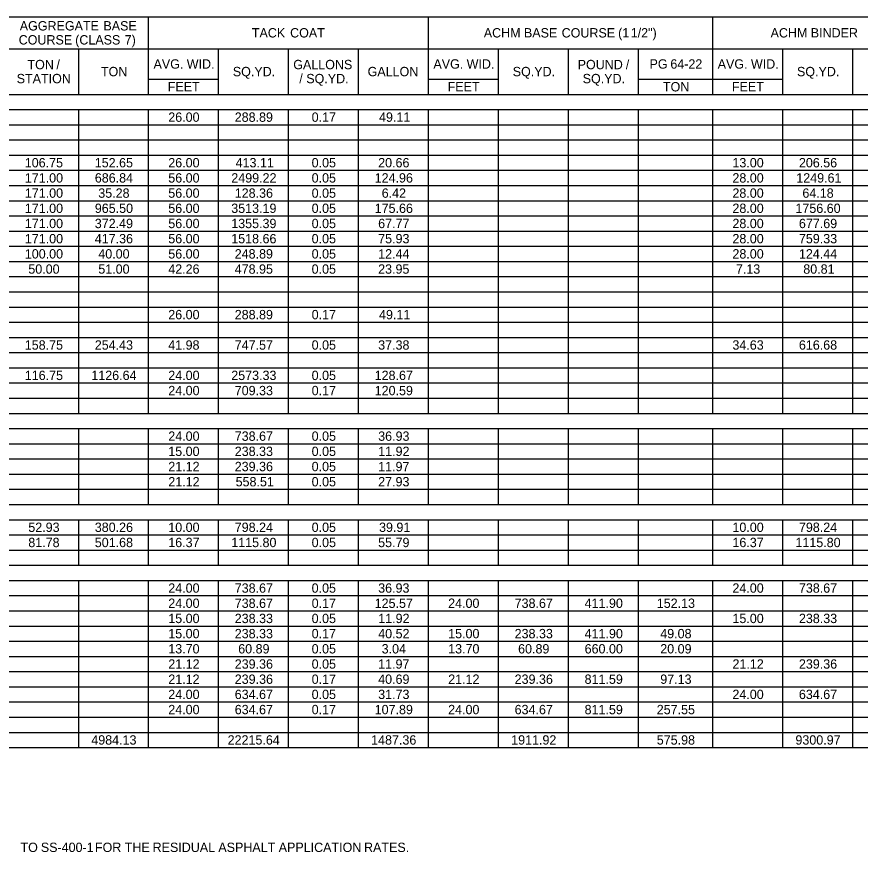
# Model space of a CAD drawing. Extents: x 1197542 to 1207068, y 230488 to 237324.
# Drawn here: x 1202093 to 1202635, y 231731 to 232267 of the extents above; entities that cross this region are included whole.
import ezdxf

# ---------------------------------------------------------------- set-up
doc = ezdxf.new("R2010")
doc.units = 0
doc.layers.add('Default', color=7, linetype='Continuous')

msp = doc.modelspace()

# ---------------------------------------------------------------- linework, layer by layer
at = {"layer": 'Default'}
for p, q in [((1201719.44, 232267.45), (1203261.96, 232267.45)), ((1202178.08, 232217.73), (1202178.08, 232267.45)), ((1202357.79, 232217.73), (1202357.79, 232267.45)), ((1202540.31, 232246.98), (1202540.31, 232267.45)), ((1202540.31, 232217.73), (1202540.31, 232267.45)), ((1202088.22, 232246.98), (1203261.96, 232246.98)), ((1202133.15, 232217.73), (1202133.15, 232246.98)), ((1202223, 232217.73), (1202223, 232246.98)), ((1202267.93, 232217.73), (1202267.93, 232246.98)), ((1202312.86, 232217.73), (1202312.86, 232246.98)), ((1202402.72, 232217.73), (1202402.72, 232246.98)), ((1202447.64, 232217.73), (1202447.64, 232246.98)), ((1202492.57, 232217.73), (1202492.57, 232246.98)), ((1202585.24, 232217.73), (1202585.24, 232246.98)), ((1202630.16, 232217.73), (1202630.16, 232246.98)), ((1202178.08, 232227.48), (1202223, 232227.48)), ((1202223, 232217.73), (1202223, 232227.48)), ((1202357.79, 232227.48), (1202402.72, 232227.48)), ((1202402.72, 232217.73), (1202402.72, 232227.48)), ((1202492.57, 232227.48), (1202585.24, 232227.48)), ((1202585.24, 232217.73), (1202585.24, 232227.48)), ((1201719.44, 232217.73), (1203261.96, 232217.73)), ((1202088.22, 232217.73), (1202223, 232217.73)), ((1202223, 232217.73), (1202402.72, 232217.73)), ((1202402.72, 232217.73), (1202585.24, 232217.73)), ((1202585.24, 232217.73), (1202767.76, 232217.73)), ((1201719.44, 232207.98), (1203261.96, 232207.98)), ((1202133.15, 232012.98), (1202133.15, 232207.98)), ((1202133.15, 232012.98), (1202133.15, 232207.98)), ((1202178.08, 232012.98), (1202178.08, 232207.98)), ((1202178.08, 232012.98), (1202178.08, 232207.98)), ((1202223, 232012.98), (1202223, 232207.98)), ((1202223, 232012.98), (1202223, 232207.98)), ((1202267.93, 232012.98), (1202267.93, 232207.98)), ((1202267.93, 232012.98), (1202267.93, 232207.98)), ((1202312.86, 232012.98), (1202312.86, 232207.98)), ((1202312.86, 232012.98), (1202312.86, 232207.98)), ((1202357.79, 232012.98), (1202357.79, 232207.98)), ((1202357.79, 232012.98), (1202357.79, 232207.98)), ((1202402.72, 232012.98), (1202402.72, 232207.98)), ((1202402.72, 232012.98), (1202402.72, 232207.98)), ((1202447.64, 232012.98), (1202447.64, 232207.98)), ((1202447.64, 232012.98), (1202447.64, 232207.98)), ((1202492.57, 232012.98), (1202492.57, 232207.98)), ((1202492.57, 232012.98), (1202492.57, 232207.98)), ((1202540.31, 232012.98), (1202540.31, 232207.98)), ((1202540.31, 232012.98), (1202540.31, 232207.98)), ((1202585.24, 232012.98), (1202585.24, 232207.98)), ((1202585.24, 232012.98), (1202585.24, 232207.98)), ((1202630.16, 232012.98), (1202630.16, 232207.98)), ((1202630.16, 232012.98), (1202630.16, 232207.98)), ((1201719.44, 232198.23), (1203261.96, 232198.23)), ((1201719.44, 232188.48), (1203261.96, 232188.48)), ((1201719.44, 232178.73), (1203261.96, 232178.73)), ((1201719.44, 232168.98), (1203261.96, 232168.98)), ((1201719.44, 232159.23), (1203261.96, 232159.23)), ((1201719.44, 232149.48), (1203261.96, 232149.48)), ((1201719.44, 232139.73), (1203261.96, 232139.73)), ((1201719.44, 232129.98), (1203261.96, 232129.98)), ((1201719.44, 232120.23), (1203261.96, 232120.23)), ((1201719.44, 232110.48), (1203261.96, 232110.48)), ((1201719.44, 232100.73), (1203261.96, 232100.73)), ((1201719.44, 232090.98), (1203261.96, 232090.98)), ((1201719.44, 232081.23), (1203261.96, 232081.23)), ((1201719.44, 232071.48), (1203261.96, 232071.48)), ((1201719.44, 232061.73), (1203261.96, 232061.73)), ((1201719.44, 232051.98), (1203261.96, 232051.98)), ((1201719.44, 232042.23), (1203261.96, 232042.23)), ((1201719.44, 232032.48), (1203261.96, 232032.48)), ((1201719.44, 232022.73), (1203261.96, 232022.73)), ((1201719.44, 232012.98), (1202992.4, 232012.98)), ((1201719.44, 232012.98), (1203261.96, 232012.98)), ((1201719.44, 232003.23), (1203261.96, 232003.23)), ((1202133.15, 231954.48), (1202133.15, 232003.23)), ((1202133.15, 231954.48), (1202133.15, 232003.23)), ((1202178.08, 231954.48), (1202178.08, 232003.23)), ((1202178.08, 231954.48), (1202178.08, 232003.23)), ((1202223, 231954.48), (1202223, 232003.23)), ((1202223, 231954.48), (1202223, 232003.23)), ((1202267.93, 231954.48), (1202267.93, 232003.23)), ((1202267.93, 231954.48), (1202267.93, 232003.23)), ((1202312.86, 231954.48), (1202312.86, 232003.23)), ((1202312.86, 231954.48), (1202312.86, 232003.23)), ((1202357.79, 231954.48), (1202357.79, 232003.23)), ((1202357.79, 231954.48), (1202357.79, 232003.23)), ((1202402.72, 231954.48), (1202402.72, 232003.23)), ((1202402.72, 231954.48), (1202402.72, 232003.23)), ((1202447.64, 231954.48), (1202447.64, 232003.23)), ((1202447.64, 231954.48), (1202447.64, 232003.23)), ((1202492.57, 231954.48), (1202492.57, 232003.23)), ((1202492.57, 231954.48), (1202492.57, 232003.23)), ((1202540.31, 231954.48), (1202540.31, 232003.23)), ((1202540.31, 231954.48), (1202540.31, 232003.23)), ((1202585.24, 231954.48), (1202585.24, 232003.23)), ((1202585.24, 231954.48), (1202585.24, 232003.23)), ((1202630.16, 231954.48), (1202630.16, 232003.23)), ((1202630.16, 231954.48), (1202630.16, 232003.23)), ((1201719.44, 231993.48), (1203261.96, 231993.48)), ((1201719.44, 231983.73), (1203261.96, 231983.73)), ((1201719.44, 231973.98), (1203261.96, 231973.98)), ((1201719.44, 231964.23), (1203261.96, 231964.23)), ((1201719.44, 231954.48), (1203261.96, 231954.48)), ((1201719.44, 231954.48), (1203261.96, 231954.48)), ((1201719.44, 231944.73), (1203261.96, 231944.73)), ((1202133.15, 231915.48), (1202133.15, 231944.73)), ((1202133.15, 231915.48), (1202133.15, 231944.73)), ((1202178.08, 231915.48), (1202178.08, 231944.73)), ((1202178.08, 231915.48), (1202178.08, 231944.73)), ((1202223, 231915.48), (1202223, 231944.73)), ((1202223, 231915.48), (1202223, 231944.73)), ((1202267.93, 231915.48), (1202267.93, 231944.73)), ((1202267.93, 231915.48), (1202267.93, 231944.73)), ((1202312.86, 231915.48), (1202312.86, 231944.73)), ((1202312.86, 231915.48), (1202312.86, 231944.73)), ((1202357.79, 231915.48), (1202357.79, 231944.73)), ((1202357.79, 231915.48), (1202357.79, 231944.73)), ((1202402.72, 231915.48), (1202402.72, 231944.73)), ((1202402.72, 231915.48), (1202402.72, 231944.73)), ((1202447.64, 231915.48), (1202447.64, 231944.73)), ((1202447.64, 231915.48), (1202447.64, 231944.73)), ((1202492.57, 231915.48), (1202492.57, 231944.73)), ((1202492.57, 231915.48), (1202492.57, 231944.73)), ((1202540.31, 231915.48), (1202540.31, 231944.73)), ((1202540.31, 231915.48), (1202540.31, 231944.73)), ((1202585.24, 231915.48), (1202585.24, 231944.73)), ((1202585.24, 231915.48), (1202585.24, 231944.73)), ((1202630.16, 231915.48), (1202630.16, 231944.73)), ((1202630.16, 231915.48), (1202630.16, 231944.73)), ((1201719.44, 231934.98), (1203261.96, 231934.98)), ((1201719.44, 231925.23), (1203261.96, 231925.23)), ((1201719.44, 231915.48), (1202992.4, 231915.48)), ((1201719.44, 231915.48), (1203261.96, 231915.48)), ((1201719.44, 231905.73), (1203261.96, 231905.73)), ((1202133.15, 231798.48), (1202133.15, 231905.73)), ((1202133.15, 231798.48), (1202133.15, 231905.73)), ((1202178.08, 231798.48), (1202178.08, 231905.73)), ((1202178.08, 231798.48), (1202178.08, 231905.73)), ((1202223, 231798.48), (1202223, 231905.73)), ((1202223, 231798.48), (1202223, 231905.73)), ((1202267.93, 231798.48), (1202267.93, 231905.73)), ((1202267.93, 231798.48), (1202267.93, 231905.73)), ((1202312.86, 231798.48), (1202312.86, 231905.73)), ((1202312.86, 231798.48), (1202312.86, 231905.73)), ((1202357.79, 231798.48), (1202357.79, 231905.73)), ((1202357.79, 231798.48), (1202357.79, 231905.73)), ((1202402.72, 231798.48), (1202402.72, 231905.73)), ((1202402.72, 231798.48), (1202402.72, 231905.73)), ((1202447.64, 231798.48), (1202447.64, 231905.73)), ((1202447.64, 231798.48), (1202447.64, 231905.73)), ((1202492.57, 231798.48), (1202492.57, 231905.73)), ((1202492.57, 231798.48), (1202492.57, 231905.73)), ((1202540.31, 231798.48), (1202540.31, 231905.73)), ((1202540.31, 231798.48), (1202540.31, 231905.73)), ((1202585.24, 231798.48), (1202585.24, 231905.73)), ((1202585.24, 231798.48), (1202585.24, 231905.73)), ((1202630.16, 231798.48), (1202630.16, 231905.73)), ((1202630.16, 231798.48), (1202630.16, 231905.73)), ((1201719.44, 231895.98), (1203261.96, 231895.98)), ((1201719.44, 231886.23), (1203261.96, 231886.23)), ((1201719.44, 231876.48), (1203261.96, 231876.48)), ((1201719.44, 231866.73), (1203261.96, 231866.73)), ((1201719.44, 231856.98), (1203261.96, 231856.98)), ((1201719.44, 231847.23), (1203261.96, 231847.23)), ((1201719.44, 231837.48), (1203261.96, 231837.48)), ((1201719.44, 231827.73), (1203261.96, 231827.73)), ((1201719.44, 231817.98), (1203261.96, 231817.98)), ((1201719.44, 231808.23), (1203261.96, 231808.23)), ((1201719.44, 231808.23), (1203261.96, 231808.23)), ((1201719.44, 231798.48), (1203261.96, 231798.48))]:
    msp.add_line(p, q, dxfattribs=at)

# ---------------------------------------------------------------- texts
for s, p in [('AGGREGATE', (1202095.31, 232258.72)), (' BASE', (1202146.79, 232258.72)), ('TACK', (1202244.33, 232254.22)), (' COAT', (1202266.67, 232254.22)), ('ACHM', (1202393.24, 232254.22)), (' BASE', (1202416.81, 232254.22)), (' COURSE', (1202441.01, 232254.22)), (' (1', (1202477.28, 232254.22)), (' 1/2")', (1202485.36, 232254.22)), ('ACHM', (1202577.39, 232254.22)), (' BINDER', (1202600.96, 232254.22)), ('COURSE', (1202094.63, 232249.72)), (' (CLASS', (1202128.67, 232249.72)), (' 7)', (1202160.46, 232249.72)), ('TON', (1202100.27, 232233.85)), (' /', (1202116.62, 232233.85)), ('AVG.', (1202181.2, 232234.23)), (' WID.', (1202200.32, 232234.23)), ('GALLONS', (1202270.92, 232233.85)), ('AVG.', (1202360.91, 232234.23)), (' WID.', (1202380.03, 232234.23)), ('POUND', (1202453.53, 232233.85)), (' /', (1202482.2, 232233.85)), ('PG', (1202499.67, 232234.23)), (' 64-22', (1202510.81, 232234.23)), ('AVG.', (1202543.43, 232234.23)), (' WID.', (1202562.55, 232234.23)), ('TON', (1202147.44, 232229.35)), ('SQ.YD.', (1202232.1, 232229.35)), ('/', (1202274.79, 232224.85)), ('GALLON', (1202318.66, 232229.35)), ('SQ.YD.', (1202411.82, 232229.35)), ('SQ.YD.', (1202594.34, 232229.35)), ('STATION', (1202093.34, 232224.85)), (' SQ.YD.', (1202277.04, 232224.85)), ('SQ.YD.', (1202456.74, 232224.85)), ('FEET', (1202190.34, 232219.6)), ('FEET', (1202370.05, 232219.6)), ('TON', (1202508.27, 232219.6)), ('FEET', (1202552.57, 232219.6)), ('26.00', (1202190.67, 232200.1)), ('288.89', (1202233.34, 232200.1)), ('0.17', (1202282.75, 232200.1)), ('49.11', (1202326, 232200.1)), ('106.75', (1202098.54, 232170.85)), ('152.65', (1202143.47, 232170.85)), ('26.00', (1202190.67, 232170.85)), ('413.11', (1202233.91, 232170.85)), ('0.05', (1202282.73, 232170.85)), ('20.66', (1202325.44, 232170.85)), ('13.00', (1202552.9, 232170.85)), ('206.56', (1202595.58, 232170.85)), ('171.00', (1202098.58, 232161.1)), ('686.84', (1202143.51, 232161.1)), ('56.00', (1202190.67, 232161.1)), ('2499.22', (1202231.14, 232161.1)), ('0.05', (1202282.73, 232161.1)), ('124.96', (1202323.2, 232161.1)), ('28.00', (1202552.9, 232161.1)), ('1249.61', (1202593.9, 232161.1)), ('171.00', (1202098.58, 232151.35)), ('35.28', (1202145.73, 232151.35)), ('56.00', (1202190.67, 232151.35)), ('128.36', (1202233.35, 232151.35)), ('0.05', (1202282.73, 232151.35)), ('6.42', (1202327.71, 232151.35)), ('28.00', (1202552.9, 232151.35)), ('64.18', (1202597.81, 232151.35)), ('171.00', (1202098.58, 232141.6)), ('965.50', (1202143.5, 232141.6)), ('56.00', (1202190.67, 232141.6)), ('3513.19', (1202231.11, 232141.6)), ('0.05', (1202282.73, 232141.6)), ('175.66', (1202323.2, 232141.6)), ('28.00', (1202552.9, 232141.6)), ('1756.60', (1202593.35, 232141.6)), ('171.00', (1202098.58, 232131.85)), ('372.49', (1202143.49, 232131.85)), ('56.00', (1202190.67, 232131.85)), ('1355.39', (1202231.11, 232131.85)), ('0.05', (1202282.73, 232131.85)), ('67.77', (1202325.44, 232131.85)), ('28.00', (1202552.9, 232131.85)), ('677.69', (1202595.58, 232131.85)), ('171.00', (1202098.58, 232122.1)), ('417.36', (1202143.49, 232122.1)), ('56.00', (1202190.67, 232122.1)), ('1518.66', (1202231.11, 232122.1)), ('0.05', (1202282.73, 232122.1)), ('75.93', (1202325.44, 232122.1)), ('28.00', (1202552.9, 232122.1)), ('759.33', (1202595.58, 232122.1)), ('100.00', (1202098.58, 232112.35)), ('40.00', (1202145.74, 232112.35)), ('56.00', (1202190.67, 232112.35)), ('248.89', (1202233.34, 232112.35)), ('0.05', (1202282.73, 232112.35)), ('12.44', (1202325.45, 232112.35)), ('28.00', (1202552.9, 232112.35)), ('124.44', (1202595.59, 232112.35)), ('50.00', (1202100.81, 232102.6)), ('51.00', (1202145.74, 232102.6)), ('42.26', (1202190.66, 232102.6)), ('478.95', (1202233.33, 232102.6)), ('0.05', (1202282.73, 232102.6)), ('23.95', (1202325.42, 232102.6)), ('7.13', (1202555.13, 232102.6)), ('80.81', (1202598.38, 232102.6)), ('26.00', (1202190.67, 232073.35)), ('288.89', (1202233.34, 232073.35)), ('0.17', (1202282.75, 232073.35)), ('49.11', (1202326, 232073.35)), ('158.75', (1202098.54, 232053.85)), ('254.43', (1202143.49, 232053.85)), ('41.98', (1202190.65, 232053.85)), ('747.57', (1202233.35, 232053.85)), ('0.05', (1202282.73, 232053.85)), ('37.38', (1202325.44, 232053.85)), ('34.63', (1202552.89, 232053.85)), ('616.68', (1202595.58, 232053.85)), ('116.75', (1202098.54, 232034.35)), ('1126.64', (1202141.27, 232034.35)), ('24.00', (1202190.67, 232034.35)), ('2573.33', (1202231.11, 232034.35)), ('0.05', (1202282.73, 232034.35)), ('128.67', (1202323.2, 232034.35)), ('24.00', (1202190.67, 232024.6)), ('709.33', (1202233.35, 232024.6)), ('0.17', (1202282.75, 232024.6)), ('120.59', (1202323.2, 232024.6)), ('24.00', (1202190.67, 231995.35)), ('738.67', (1202233.35, 231995.35)), ('0.05', (1202282.73, 231995.35)), ('36.93', (1202325.44, 231995.35)), ('15.00', (1202190.67, 231985.6)), ('238.33', (1202233.35, 231985.6)), ('0.05', (1202282.73, 231985.6)), ('11.92', (1202325.47, 231985.6)), ('21.12', (1202190.69, 231975.85)), ('239.36', (1202233.35, 231975.85)), ('0.05', (1202282.73, 231975.85)), ('11.97', (1202325.44, 231975.85)), ('21.12', (1202190.69, 231966.1)), ('558.51', (1202233.91, 231966.1)), ('0.05', (1202282.73, 231966.1)), ('27.93', (1202325.44, 231966.1)), ('52.93', (1202100.8, 231936.85)), ('380.26', (1202143.49, 231936.85)), ('10.00', (1202190.67, 231936.85)), ('798.24', (1202233.36, 231936.85)), ('0.05', (1202282.73, 231936.85)), ('39.91', (1202326, 231936.85)), ('10.00', (1202552.9, 231936.85)), ('798.24', (1202595.59, 231936.85)), ('81.78', (1202100.8, 231927.1)), ('501.68', (1202143.49, 231927.1)), ('16.37', (1202190.66, 231927.1)), ('1115.80', (1202231.12, 231927.1)), ('0.05', (1202282.73, 231927.1)), ('55.79', (1202325.44, 231927.1)), ('16.37', (1202552.89, 231927.1)), ('1115.80', (1202593.35, 231927.1)), ('24.00', (1202190.67, 231897.85)), ('738.67', (1202233.35, 231897.85)), ('0.05', (1202282.73, 231897.85)), ('36.93', (1202325.44, 231897.85)), ('24.00', (1202552.9, 231897.85)), ('738.67', (1202595.58, 231897.85)), ('24.00', (1202190.67, 231888.1)), ('738.67', (1202233.35, 231888.1)), ('0.17', (1202282.75, 231888.1)), ('125.57', (1202323.2, 231888.1)), ('24.00', (1202370.38, 231888.1)), ('738.67', (1202413.06, 231888.1)), ('411.90', (1202458, 231888.1)), ('152.13', (1202504.32, 231888.1)), ('15.00', (1202190.67, 231878.35)), ('238.33', (1202233.35, 231878.35)), ('0.05', (1202282.73, 231878.35)), ('11.92', (1202325.47, 231878.35)), ('15.00', (1202552.9, 231878.35)), ('238.33', (1202595.58, 231878.35)), ('15.00', (1202190.67, 231868.6)), ('238.33', (1202233.35, 231868.6)), ('0.17', (1202282.75, 231868.6)), ('40.52', (1202325.47, 231868.6)), ('15.00', (1202370.38, 231868.6)), ('238.33', (1202413.06, 231868.6)), ('411.90', (1202458, 231868.6)), ('49.08', (1202506.55, 231868.6)), ('13.70', (1202190.67, 231858.85)), ('60.89', (1202235.58, 231858.85)), ('0.05', (1202282.73, 231858.85)), ('3.04', (1202327.69, 231858.85)), ('13.70', (1202370.38, 231858.85)), ('60.89', (1202415.29, 231858.85)), ('660.00', (1202458, 231858.85)), ('20.09', (1202506.55, 231858.85)), ('21.12', (1202190.69, 231849.1)), ('239.36', (1202233.35, 231849.1)), ('0.05', (1202282.73, 231849.1)), ('11.97', (1202325.44, 231849.1)), ('21.12', (1202552.92, 231849.1)), ('239.36', (1202595.58, 231849.1)), ('21.12', (1202190.69, 231839.35)), ('239.36', (1202233.35, 231839.35)), ('0.17', (1202282.75, 231839.35)), ('40.69', (1202325.44, 231839.35)), ('21.12', (1202370.4, 231839.35)), ('239.36', (1202413.06, 231839.35)), ('811.59', (1202457.98, 231839.35)), ('97.13', (1202506.56, 231839.35)), ('24.00', (1202190.67, 231829.6)), ('634.67', (1202233.35, 231829.6)), ('0.05', (1202282.73, 231829.6)), ('31.73', (1202325.44, 231829.6)), ('24.00', (1202552.9, 231829.6)), ('634.67', (1202595.58, 231829.6)), ('24.00', (1202190.67, 231819.85)), ('634.67', (1202233.35, 231819.85)), ('0.17', (1202282.75, 231819.85)), ('107.89', (1202323.2, 231819.85)), ('24.00', (1202370.38, 231819.85)), ('634.67', (1202413.06, 231819.85)), ('811.59', (1202457.98, 231819.85)), ('257.55', (1202504.3, 231819.85)), ('4984.13', (1202141.25, 231800.35)), ('22215.64', (1202228.79, 231800.35)), ('1487.36', (1202320.93, 231800.35)), ('1911.92', (1202410.84, 231800.35)), ('575.98', (1202504.32, 231800.35)), ('9300.97', (1202593.34, 231800.35)), (' TO', (1202093.56, 231731.43)), (' SS-400-1', (1202106.62, 231731.43)), (' FOR', (1202141.36, 231731.43)), (' THE', (1202160.48, 231731.43)), (' RESIDUAL', (1202178.38, 231731.43)), (' ASPHALT', (1202220.58, 231731.43)), (' APPLICATION', (1202259.34, 231731.43)), (' RATES.', (1202314.14, 231731.43))]:
    msp.add_text(s, height=6, dxfattribs=at).set_placement(p)

doc.saveas('drawing.dxf')
